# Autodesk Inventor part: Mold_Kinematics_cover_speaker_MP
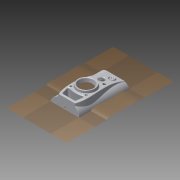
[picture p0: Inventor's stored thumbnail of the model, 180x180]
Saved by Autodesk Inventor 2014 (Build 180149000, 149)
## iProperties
Created: 2009-12
Part Number: Mold_Kinematics_cover_speaker_MP
Document SubType Name: Modeling
Designer: gaom
Density: 1 g/cm^3
Material: Generic
Appearance: Default
Author: gaom
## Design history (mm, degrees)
derived "cover_speaker.ipt"
node "Mold_Kinematics_cover_speaker_WP"
patch "Boundary Patch1" dims "d21" = 10, "d22" = 0
patch "Boundary Patch2" dims "d31" = 10, "d32" = 0
node "Hole Patch1"
node "Hole Patch2"
node "Hole Patch3"
node "Hole Patch4"
patch "Boundary Patch3" dims "d35" = 10, "d42" = 10, "d45" = 10, "d48" = 10, "d49" = 0
patch "Boundary Patch4" dims "d50" = 10, "d51" = 10, "d52" = 10, "d72" = 10, "d82" = 10, "d85" = 10, "d92" = 10, "d95" = 10, "d97" = 0
node "Runoff1" dims "Xmax" = 79, "Xmin" = -79, "Ymax" = 140, "Ymin" = -140, "Zmax" = 31.5, "Zmin" = -31.5
node "Runoff2" dims "Xmax" = 79, "Xmin" = -79, "Ymax" = 140, "Ymin" = -140, "Zmax" = 31.5, "Zmin" = -31.5
node "Runoff3" dims "Xmax" = 79, "Xmin" = -79, "Ymax" = 140, "Ymin" = -140, "Zmax" = 31.5, "Zmin" = -31.5
node "Runoff4" dims "Xmax" = 79, "Xmin" = -79, "Ymax" = 140, "Ymin" = -140, "Zmax" = 31.5, "Zmin" = -31.5
node "Runoff5" dims "Xmax" = 79, "Xmin" = -79, "Ymax" = 140, "Ymin" = -140, "Zmax" = 31.5, "Zmin" = -31.5
node "Runoff6" dims "Xmax" = 79, "Xmin" = -79, "Ymax" = 140, "Ymin" = -140, "Zmax" = 31.5, "Zmin" = -31.5
node "Runoff7" dims "Xmax" = 79, "Xmin" = -79, "Ymax" = 140, "Ymin" = -140, "Zmax" = 31.5, "Zmin" = -31.5
node "Runoff8" dims "Xmax" = 79, "Xmin" = -79, "Ymax" = 140, "Ymin" = -140, "Zmax" = 31.5, "Zmin" = -31.5
node "Runoff9" dims "Xmax" = 79, "Xmin" = -79, "Ymax" = 140, "Ymin" = -140, "Zmax" = 31.5, "Zmin" = -31.5
node "Runoff10" dims "Xmax" = 79, "Xmin" = -79, "Ymax" = 140, "Ymin" = -140, "Zmax" = 31.5, "Zmin" = -31.5
node "Runoff11" dims "Xmax" = 79, "Xmin" = -79, "Ymax" = 140, "Ymin" = -140, "Zmax" = 31.5, "Zmin" = -31.5
node "Runoff12" dims "Xmax" = 79, "Xmin" = -79, "Ymax" = 140, "Ymin" = -140, "Zmax" = 31.5, "Zmin" = -31.5
node "Runoff13" dims "Xmax" = 79, "Xmin" = -79, "Ymax" = 140, "Ymin" = -140, "Zmax" = 31.5, "Zmin" = -31.5
node "Runoff14" dims "Xmax" = 79, "Xmin" = -79, "Ymax" = 140, "Ymin" = -140, "Zmax" = 31.5, "Zmin" = -31.5
node "Runoff15" dims "Xmax" = 79, "Xmin" = -79, "Ymax" = 140, "Ymin" = -140, "Zmax" = 31.5, "Zmin" = -31.5
node "Runoff16" dims "Xmax" = 79, "Xmin" = -79, "Ymax" = 140, "Ymin" = -140, "Zmax" = 31.5, "Zmin" = -31.5
feature "Cavity Separation1"
node "Mold_Kinematics_cover_speaker_IN1_Base"
feature "Solid1::cover_speaker.ipt"
tag "TaggingFeature1"
feature "Solid1::Mold_Kinematics_cover_speaker_WP"
tag "TaggingFeature2"
body "Srf1"
body "Srf2"
body "Srf7"
body "Srf8"
body "Solid3"
body "Solid4"
feature "Solid2::Mold_Kinematics_cover_speaker_IN1_Base"
tag "TaggingFeature3"
body "Solid1"
body "Solid2"
feature "Surface1"
body "Srf3"
feature "Surface2"
body "Srf4"
feature "Surface3"
body "Srf5"
feature "Surface4"
body "Srf6"
feature "Surface5"
body "Srf9"
feature "Surface6"
body "Srf10"
feature "Surface7"
body "Srf11"
feature "Surface8"
body "Srf12"
feature "Surface9"
body "Srf13"
feature "Surface10"
body "Srf14"
feature "Surface11"
body "Srf15"
feature "Surface12"
body "Srf16"
feature "Surface13"
body "Srf17"
feature "Surface14"
body "Srf18"
feature "Surface15"
body "Srf19"
feature "Surface16"
body "Srf20"
feature "Surface17"
body "Srf21"
feature "Surface18"
body "Srf22"
feature "Surface19"
body "Srf23"
feature "Surface20"
body "Srf24"
body "Solid5"
other parameters: "d241" = 33.959, "d242" = 1, "d244" = 1 deg, "d254" = 2.25, "d255" = 11.25, "d256" = 11.25, "d257" = 4.704, "d258" = 4.95, "d260" = 0, "d210" = 1, "d211" = 2.884, "d212" = 1.697, "d213" = 15, "d214" = -1 deg, "d216" = 360 deg, "d224" = 0, "d226" = 4, "d227" = 0, "d229" = 1.75, "d230" = 6.792, "d231" = 45.599, "d232" = 1, "d234" = 1 deg, "d237" = 22.64, "d238" = 0, "d239" = 11.32, "d240" = 88.363, "d175" = 2.264, "d180" = 5.16, "d182" = 2 deg, "d183" = 18 deg, "d190" = 1, "d191" = 0, "d192" = 3, "d193" = 5, "d194" = 2, "d195" = 7.5, "d196" = 2, "d197" = 2.5, "d200" = 1, "d201" = 0, "d202" = 3, "d203" = 5, "d204" = 2, "d205" = 7.5, "d206" = 2, "d207" = 2.5, "d208" = 38, "d209" = 0.4, "d151" = 44.86682, "d152" = 3, "d153" = 3, "d154" = 1, "d155" = 1, "d156" = 1, "d158" = 1, "d169" = 1, "d171" = 5.5, "d172" = -2 deg, "d144" = 54.1, "d145" = 5, "d146" = 1.5, "d147" = 4, "d148" = 54.67592, "d149" = 25.58531, "d150" = 4, "d123" = 80 deg, "d124" = 35, "d125" = -27, "d126" = -1.5, "d127" = 0, "d128" = 90 deg, "d129" = 0, "d130" = 90 deg, "d139" = 2, "d142" = 2, "d143" = 2, "d94" = 6.2, "d96" = -2 deg, "d98" = 35, "d99" = -22.8, "d101" = -30 deg, "d103" = 88.795, "d104" = 13.762, "d105" = 25, "d107" = -2 deg, "d108" = 21, "d110" = -15 deg, "d112" = 5.5, "d118" = 3.396, "d119" = 4.802, "d120" = 3.345, "d122" = 0, "d74" = 57.968, "d75" = 11.32, "d76" = -20 deg, "d77" = -26, "d78" = -31.5, "d81" = 8.415, "d83" = -2 deg, "d84" = 3, "d86" = -2 deg, "d87" = 23.384, "d88" = 47.477, "d89" = 11.698, "d90" = -24, "d91" = -15.5, "d93" = -2 deg, "d58" = 90 deg, "d59" = 12 deg, "d60" = 1.132, "d61" = 1.129, "d62" = 4.851, "d63" = 4.5, "d64" = 2.8, "d65" = 39, "d66" = 97, "d67" = 16, "d68" = 32, "d69" = 75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
